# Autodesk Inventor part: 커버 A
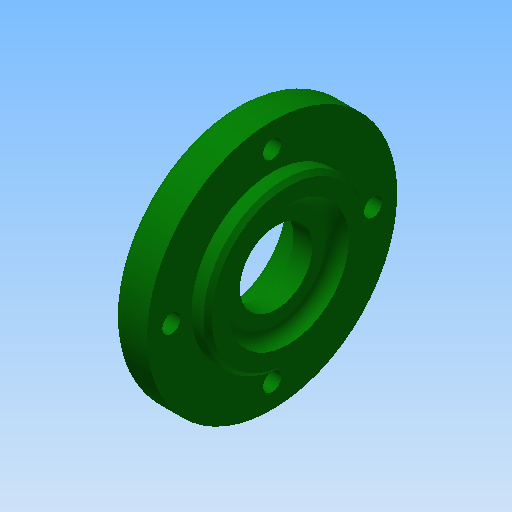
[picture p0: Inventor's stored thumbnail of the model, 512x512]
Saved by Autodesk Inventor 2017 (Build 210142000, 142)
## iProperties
Created: 2019-01
Part Number: 커버 A
Material: 알루미늄 6061
Document SubType Name: Modeling
Designer: mduedu
Density: 2.71 g/cm^3
Mass: 67.6019 g
Surface Area: 94.4617 cm^2
Volume: 24.9453 cm^3
Appearance: 진녹색
Author: mduedu
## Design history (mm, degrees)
sketch "스케치1"
  geometry: L1 (0, 0)-(9, 0); L2 (9, 0)-(9, 31); L3 (9, 31)-(0, 31); L4 (0, 31)-(0, 0); L5 (9, 0)-(13, 0); L6 (13, 0)-(13, 20); L7 (13, 20)-(9, 20); L8 (9, 20)-(9, 0)
  constraints: 16 end point, 4 parallel, 2 horizontal, 2 perpendicular
  dimensions: "d0" = 13 distance between parallel lines of L6 L4; "d2" = 62 diameter of L3 L1; "d3" = 40 diameter of L7 L5; "d4" = 4 distance between parallel lines of L6 L2
revolve "회전1" sketch "스케치1" stored, may be unused: angle "d5" = 90 deg
sketch "스케치5"
  geometry: C1 r 19 at (0, 0); 1 further point
  constraints: 1 centre point, 1 coincident
  dimensions: "d34" = 38 diameter of C1
extrude "돌출1" join sketch "스케치5" distance "d35" = 3; taper "d36" = 0 deg
sketch "스케치2"
  geometry: L1 (9, -20)-(9, -31) reference; L2 (9, -31)-(0, -31) reference; L3 (0, -31)-(0, -19) reference; L4 (0, -19)-(-3, -19) reference; L5 (-3, -19)-(-3, 19) reference; L6 (-3, 19)-(0, 19) reference; L7 (0, 19)-(0, 31) reference; L8 (0, 31)-(9, 31) reference; L9 (9, 31)-(9, 20) reference; L10 (9, 20)-(13, 20) reference; L11 (13, 20)-(13, -20) reference; L12 (13, -20)-(9, -20) reference; L13 (-3, 0)-(5.3, 0); L14 (5.3, 0)-(5.3, 15); L15 (5.3, 15)-(-3, 15); L16 (-3, 15)-(-3, 0); L17 (5.3, 0)-(10, 0); L18 (10, 0)-(10, 9); L19 (10, 9)-(5.3, 9); L20 (5.3, 9)-(5.3, 0); L21 (10, 0)-(13, 0); L22 (13, 0)-(13, 15); L23 (13, 15)-(10, 15); L24 (10, 15)-(10, 0)
  constraints: 24 end point, 6 parallel, 3 horizontal, 3 perpendicular, 1 midpoint, 1 point on line
  dimensions: "d38" = 30 diameter of L15 L13; "d40" = 30 diameter of L23 L21; "d41" = 3 distance of L22.end L23.end; "d42" = 8.3 distance of L14.end L15.end; "d43" = 18 diameter of L19 L17
revolve "회전2" sketch "스케치2" stored, may be unused: angle "d12" = 90 deg
chamfer "모따기1" distance "d13" = 0.8; stored, may be unused: second distance "d14" = 2, angle "d15" = 30 deg
fillet "모깎기1" dims "d16" = 0.5
fillet "모깎기2" dims "d17" = 3
fillet "모깎기3" dims "d18" = 3
chamfer "모따기2" distance "d24" = 1; stored, may be unused: second distance "d25" = 2, angle "d26" = 45 deg
sketch "스케치3" dims "d19" = 50
  geometry: 6 further points
  constraints: 2 vertical alignment, 1 coincident, 7 other
  dimensions: "d22" = 360 deg dimension on point (0, 0) point (0, 25) (derived)
sketch "스케치4"
  geometry: 4 further points
  constraints: 4 other
hole "구멍1" sketch "스케치4" at (-25, 0), (0, -25), (25, 0), (0, 25) diameter "d27" = 4.5; stored, may be unused: countersink angle "d31" = 90 deg, drill point angle "d33" = 0 deg; dims "d28" = 6, "d29" = 8, "d30" = 4.6, "d32" = 8
fillet "모깎기6" dims "d47" = 1
node "솔리드1"
node "절단 모서리 투영2"
